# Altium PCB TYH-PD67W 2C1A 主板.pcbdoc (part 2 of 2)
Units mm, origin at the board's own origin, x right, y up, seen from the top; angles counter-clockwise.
Board outline 94.32 x 66.89 mm, 5 copper layers (Top Layer, Signal Layer 3, Signal Layer 1, Signal Layer 2, Bottom Layer), stack 0.941 mm thick; 52 components, 153 nets, 152 pads, 297 vias.
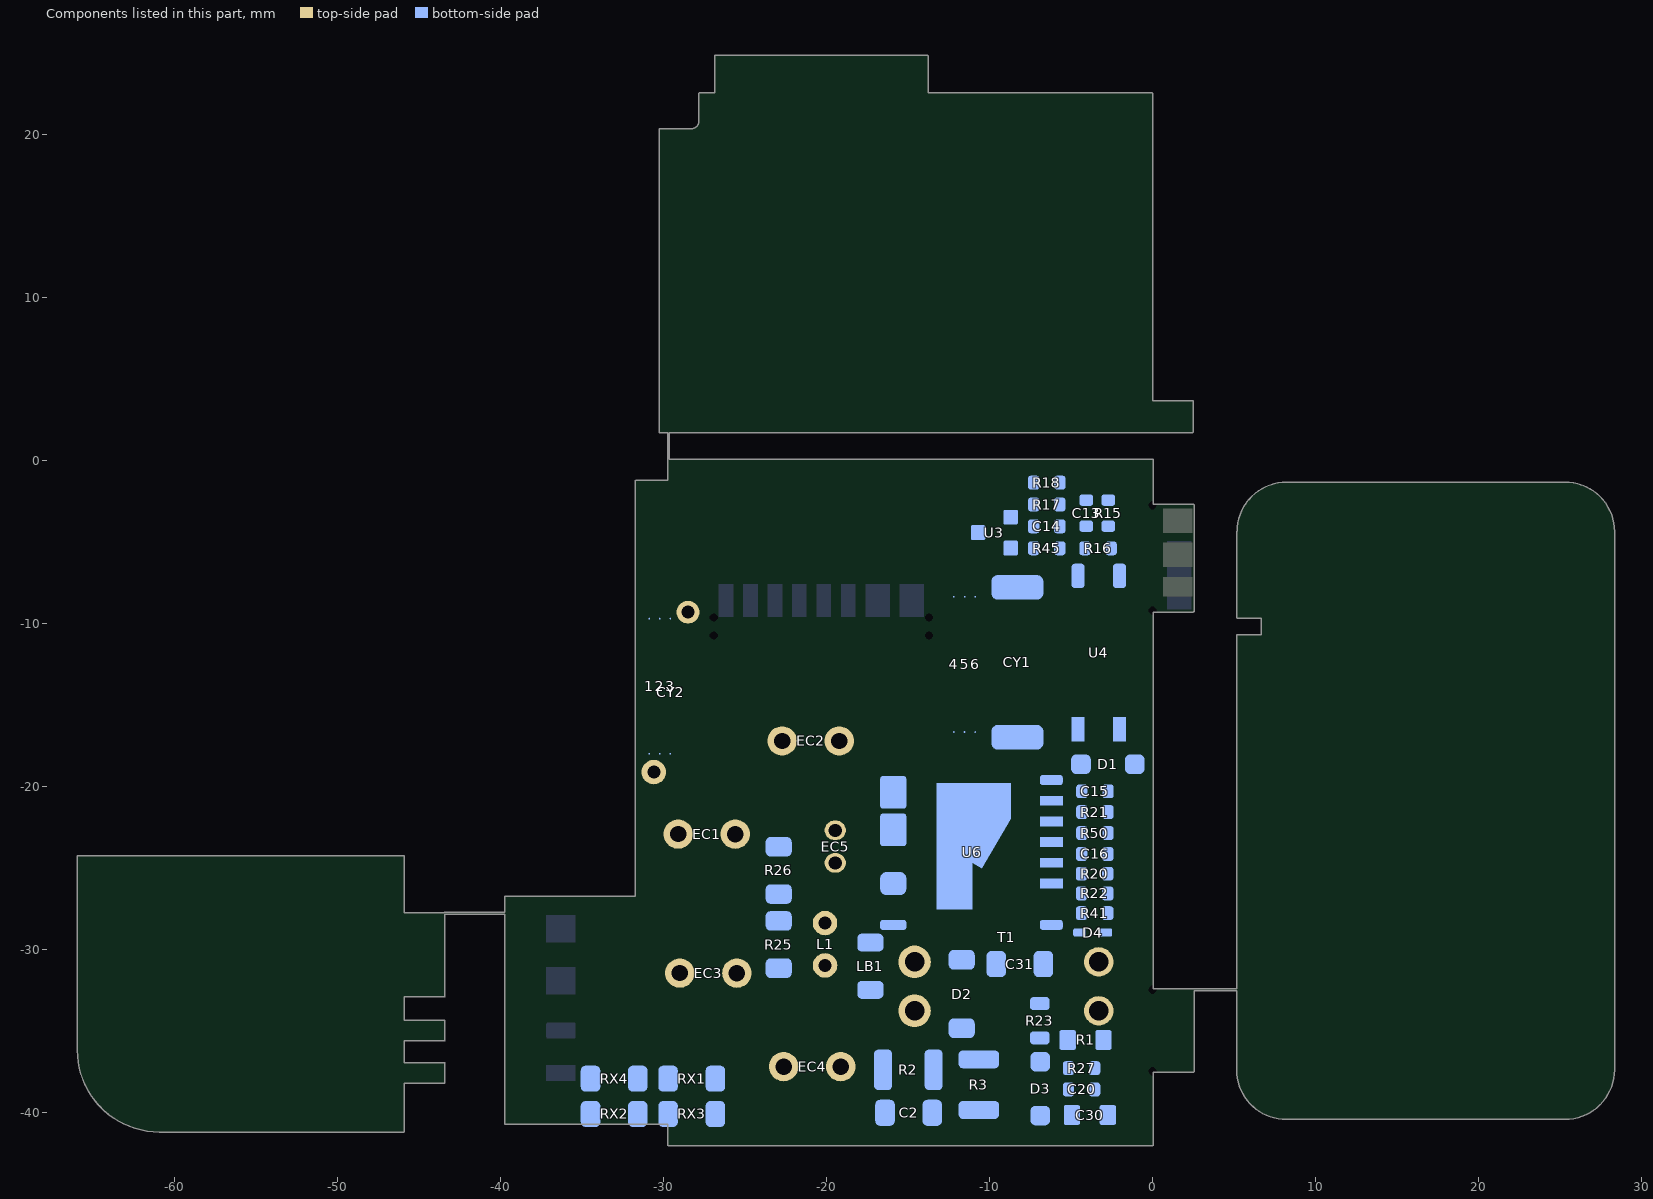
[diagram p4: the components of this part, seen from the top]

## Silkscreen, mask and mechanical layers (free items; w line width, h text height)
Top Overlay:
  circle w0.05: c-3.303,-27.787 r2
  lines w0.05: -38.25,-41.5 -38.25,-26.8 ; -37.25,-41.5 -37.25,-26.8 ; -37.25,-39.04 -29.75,-39.04 -29.75,-34.64 -37.25,-34.64 ; -37.25,-34.397 -37.25,-24.397 -31.85,-24.397 -31.85,-34.397 -37.25,-34.397
  lines w0.1: -31.7,-10.714 0,-10.714 ; -31.7,-9.714 0,-9.714 ; -29.709,-41.459 0.001,-41.459 ; -29.7,-0.55 0,-0.55 ; -27.175,-9.714 -27.175,0.336 ; -21.452,-9.714 -21.452,0.336 ; -16.876,-9.714 -16.876,0.336 ; -13.666,-9.714 -13.666,0.336 ; -8.876,-9.706 -8.876,0.344 ; -5.666,-9.706 -5.666,0.344 ; 0.05,-40.406 1.05,-40.406 1.05,-1.387 0.05,-1.387 0.05,-40.406
Bottom Solder:
  region: -18.056,-23.697 -15.131,-23.697 -15.002,-23.569 -15.002,-18.857 -15.325,-18.534 -17.635,-18.534 -18.044,-18.943 -19.37,-18.943 -19.891,-19.465 -19.891,-21.118 -19.519,-21.491 -18.774,-21.491 -18.253,-22.012 -18.253,-23.5
  region: -13.503,-27.722 -13.503,-19.684 -8.571,-19.684 -8.571,-21.994 -10.439,-25.22 -10.439,-27.722
  lines w1: -34.018,-28.59 -32.764,-28.59 ; -31.192,-28.441 -30.172,-27.421 ; -29.585,-26.155 -29.585,-24.984 ; -28.467,-21.222 -28.467,-21.024 -27.109,-19.666 ; -27.833,-29.533 -26.384,-28.084 ; -26.041,-26.569 -26.041,-24.985 ; -25.751,-18.506 -24.79,-17.545 ; -21.373,-33.069 -20.494,-33.947 ; -19.599,-35.019 -17.087,-35.019 ; -15.658,-34.843 -14.603,-33.787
